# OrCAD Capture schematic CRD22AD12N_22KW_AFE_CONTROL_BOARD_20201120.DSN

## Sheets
1 P4 Output voltage sampling: size A3; title: 22kW Three Phase Bi-directional AFE ACDC Control Board; rev: 0v1; note: P/N: CRD22AD12N
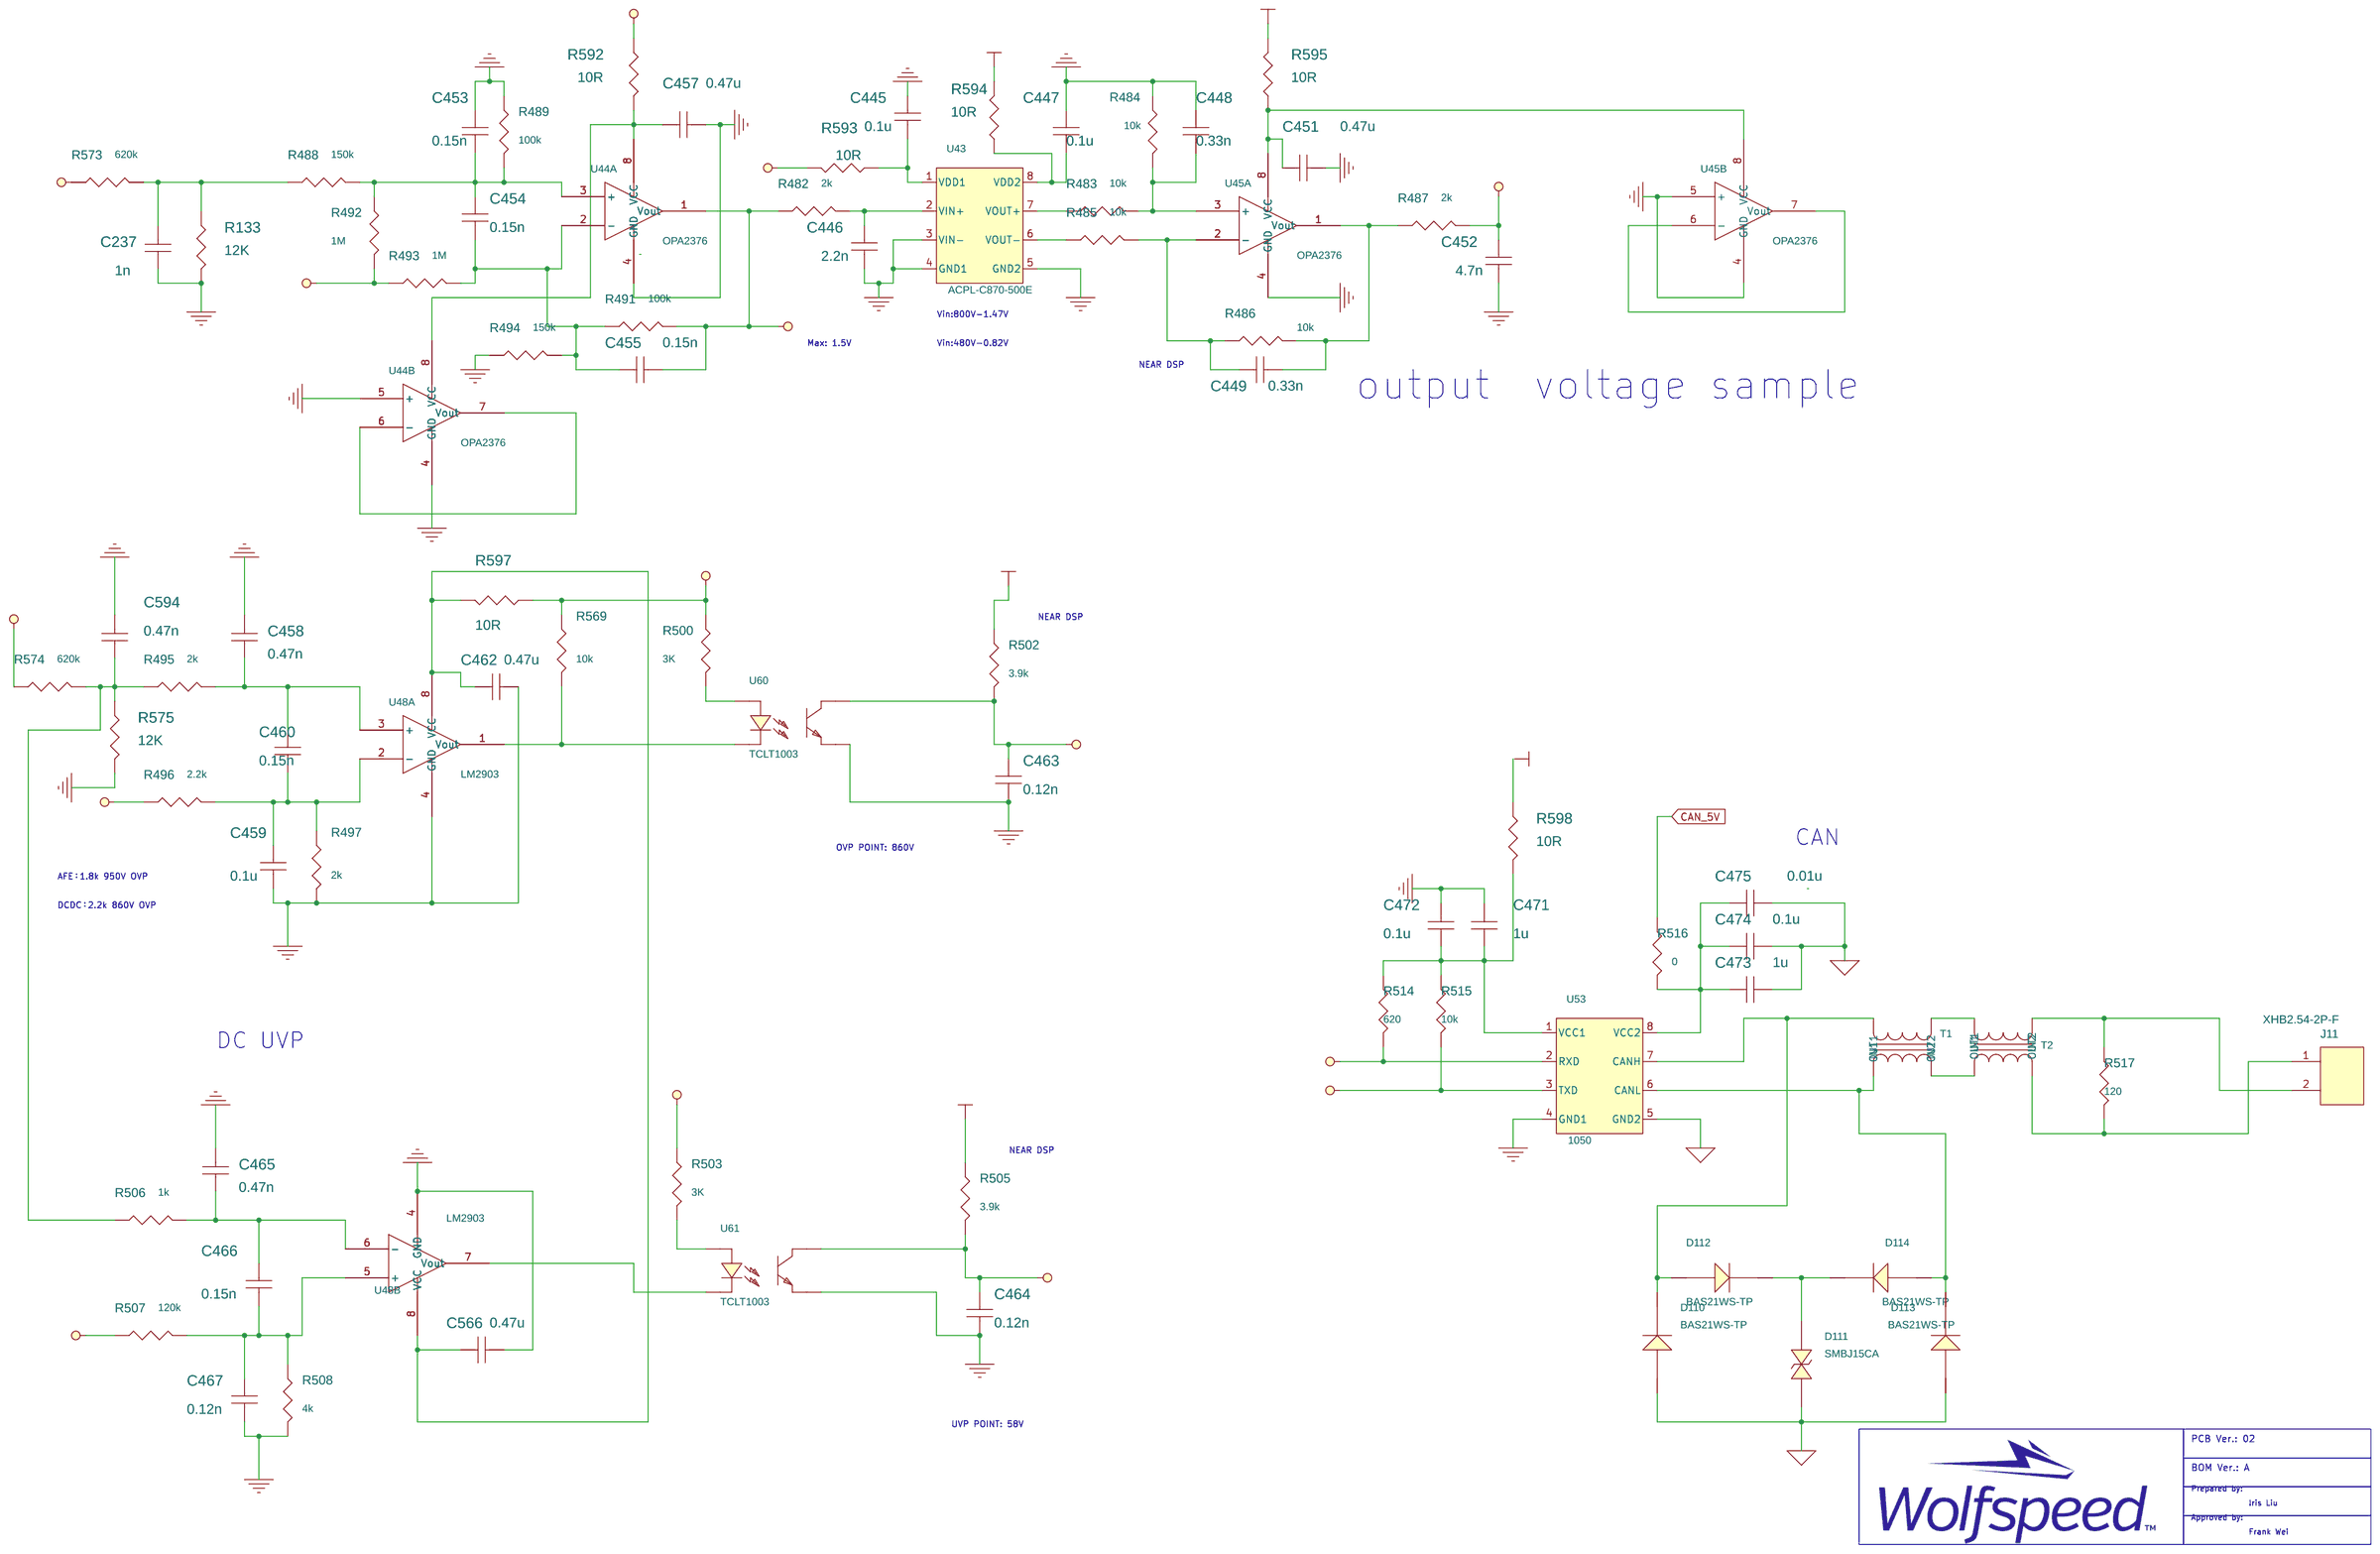
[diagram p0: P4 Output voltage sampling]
2 P3 Connector and Power supply: size A3
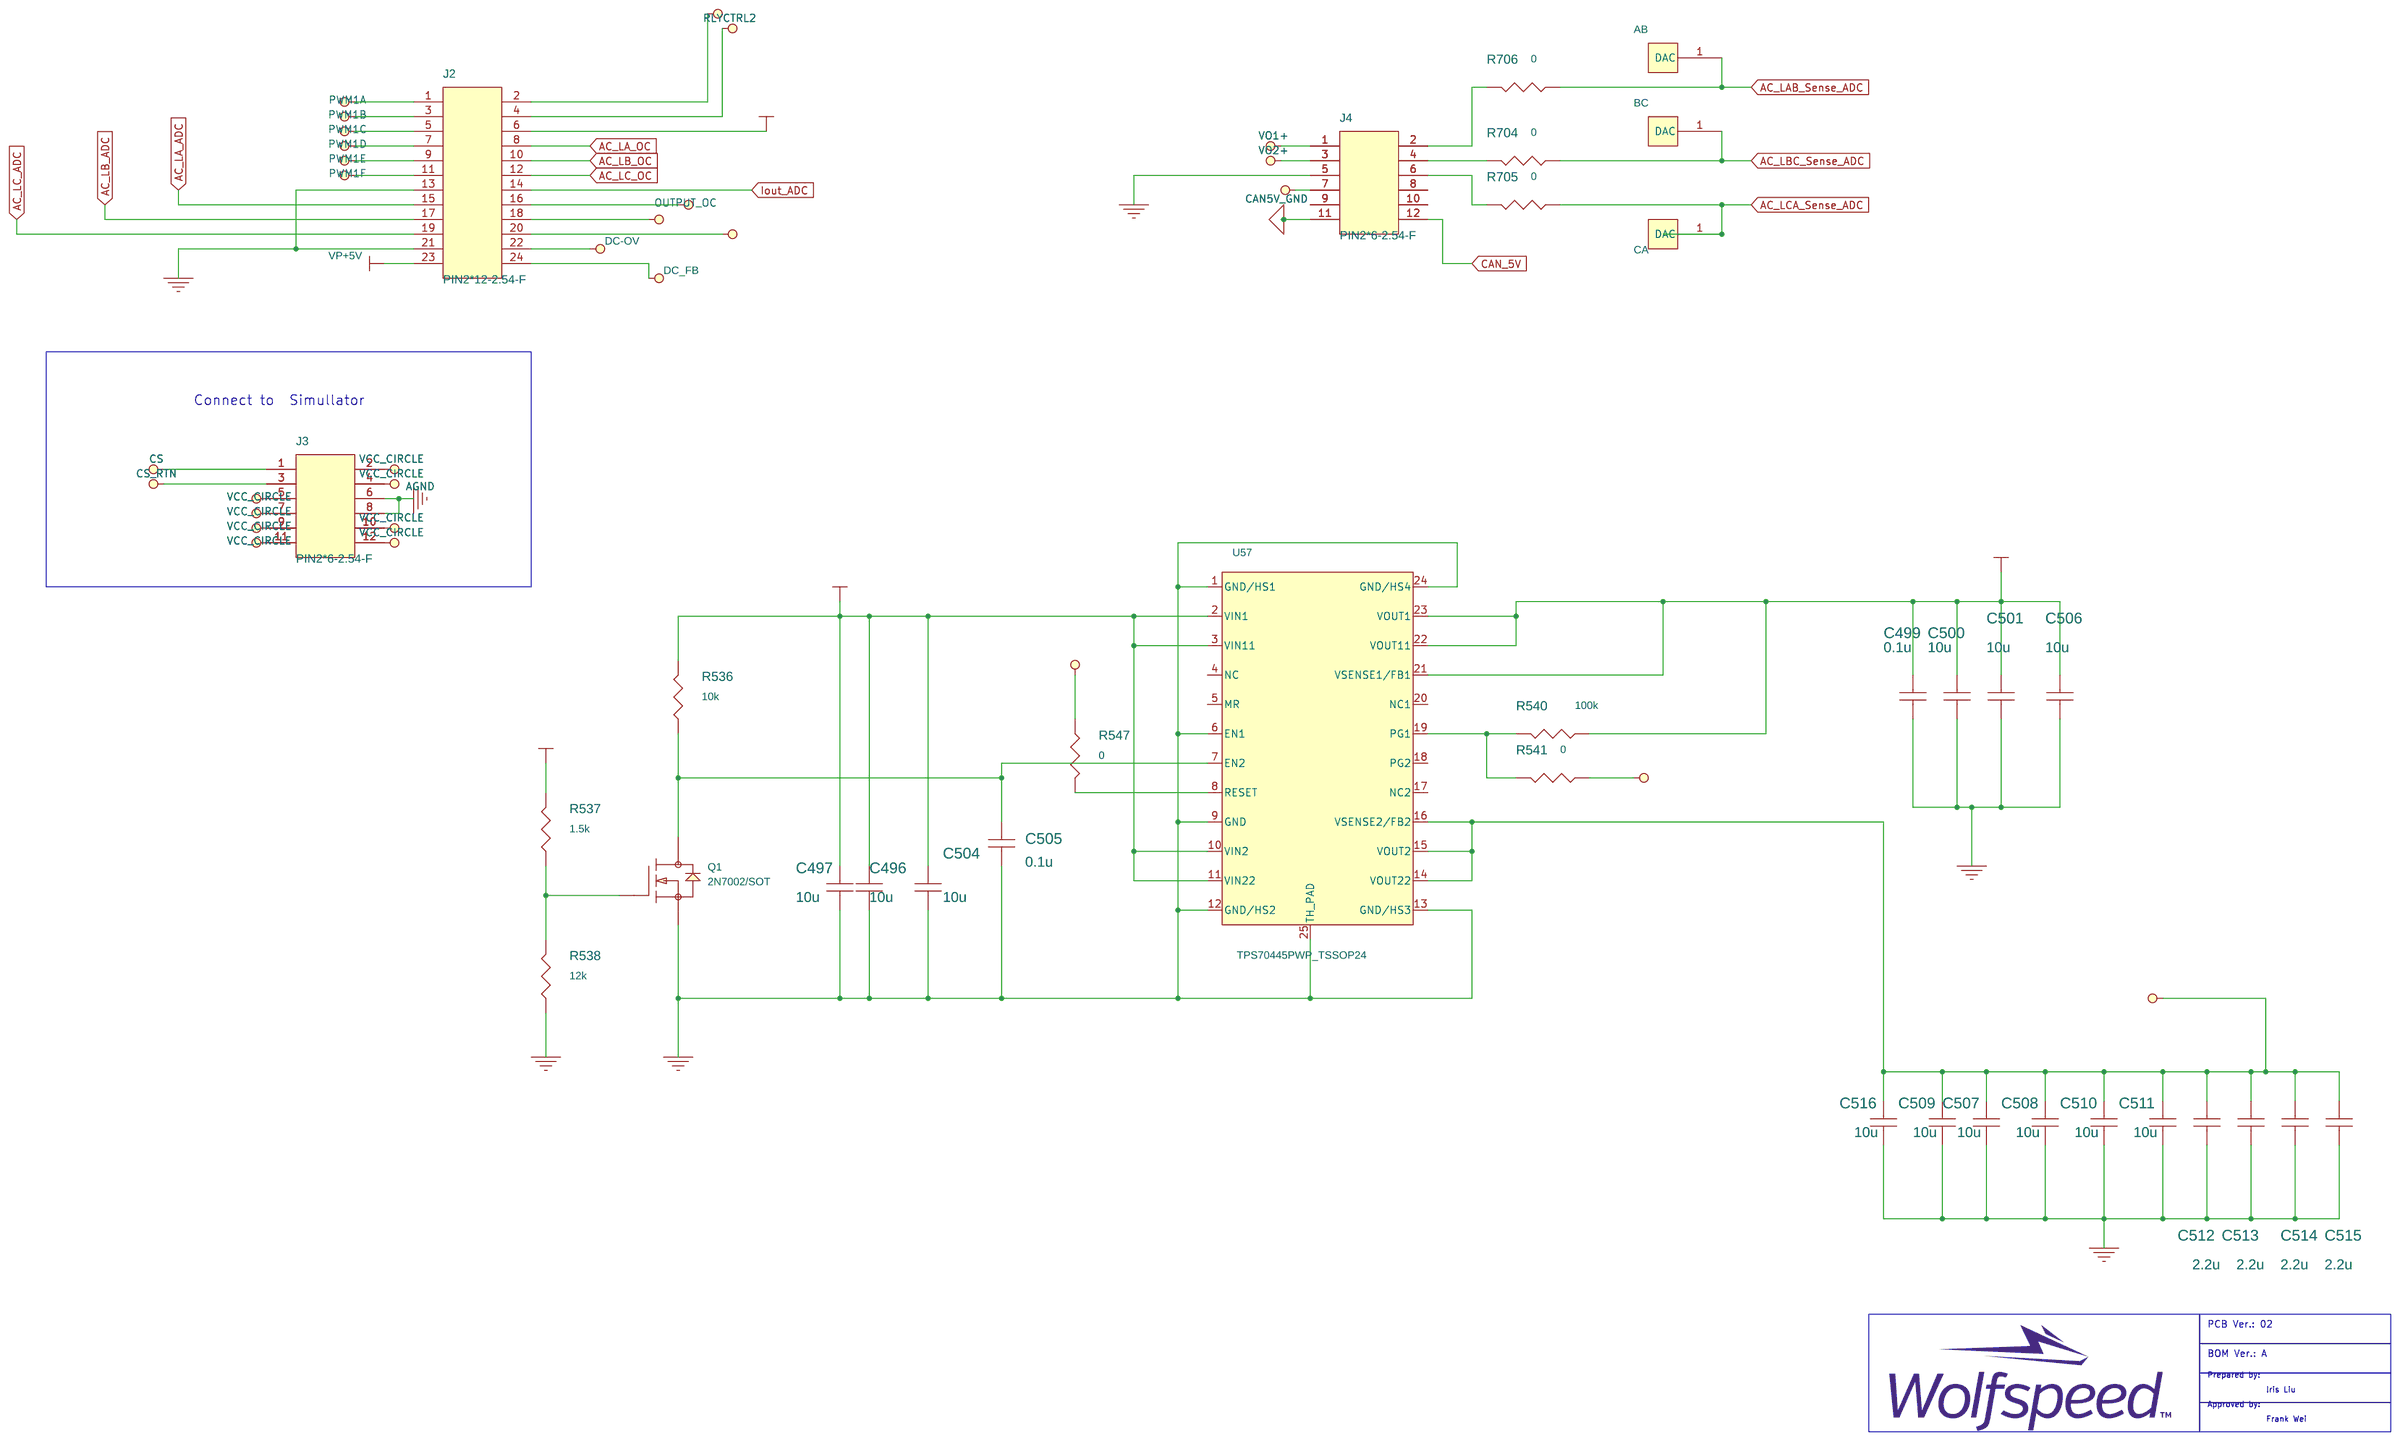
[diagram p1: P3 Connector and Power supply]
3 P2 Bus voltage sampling EPROM: size A3
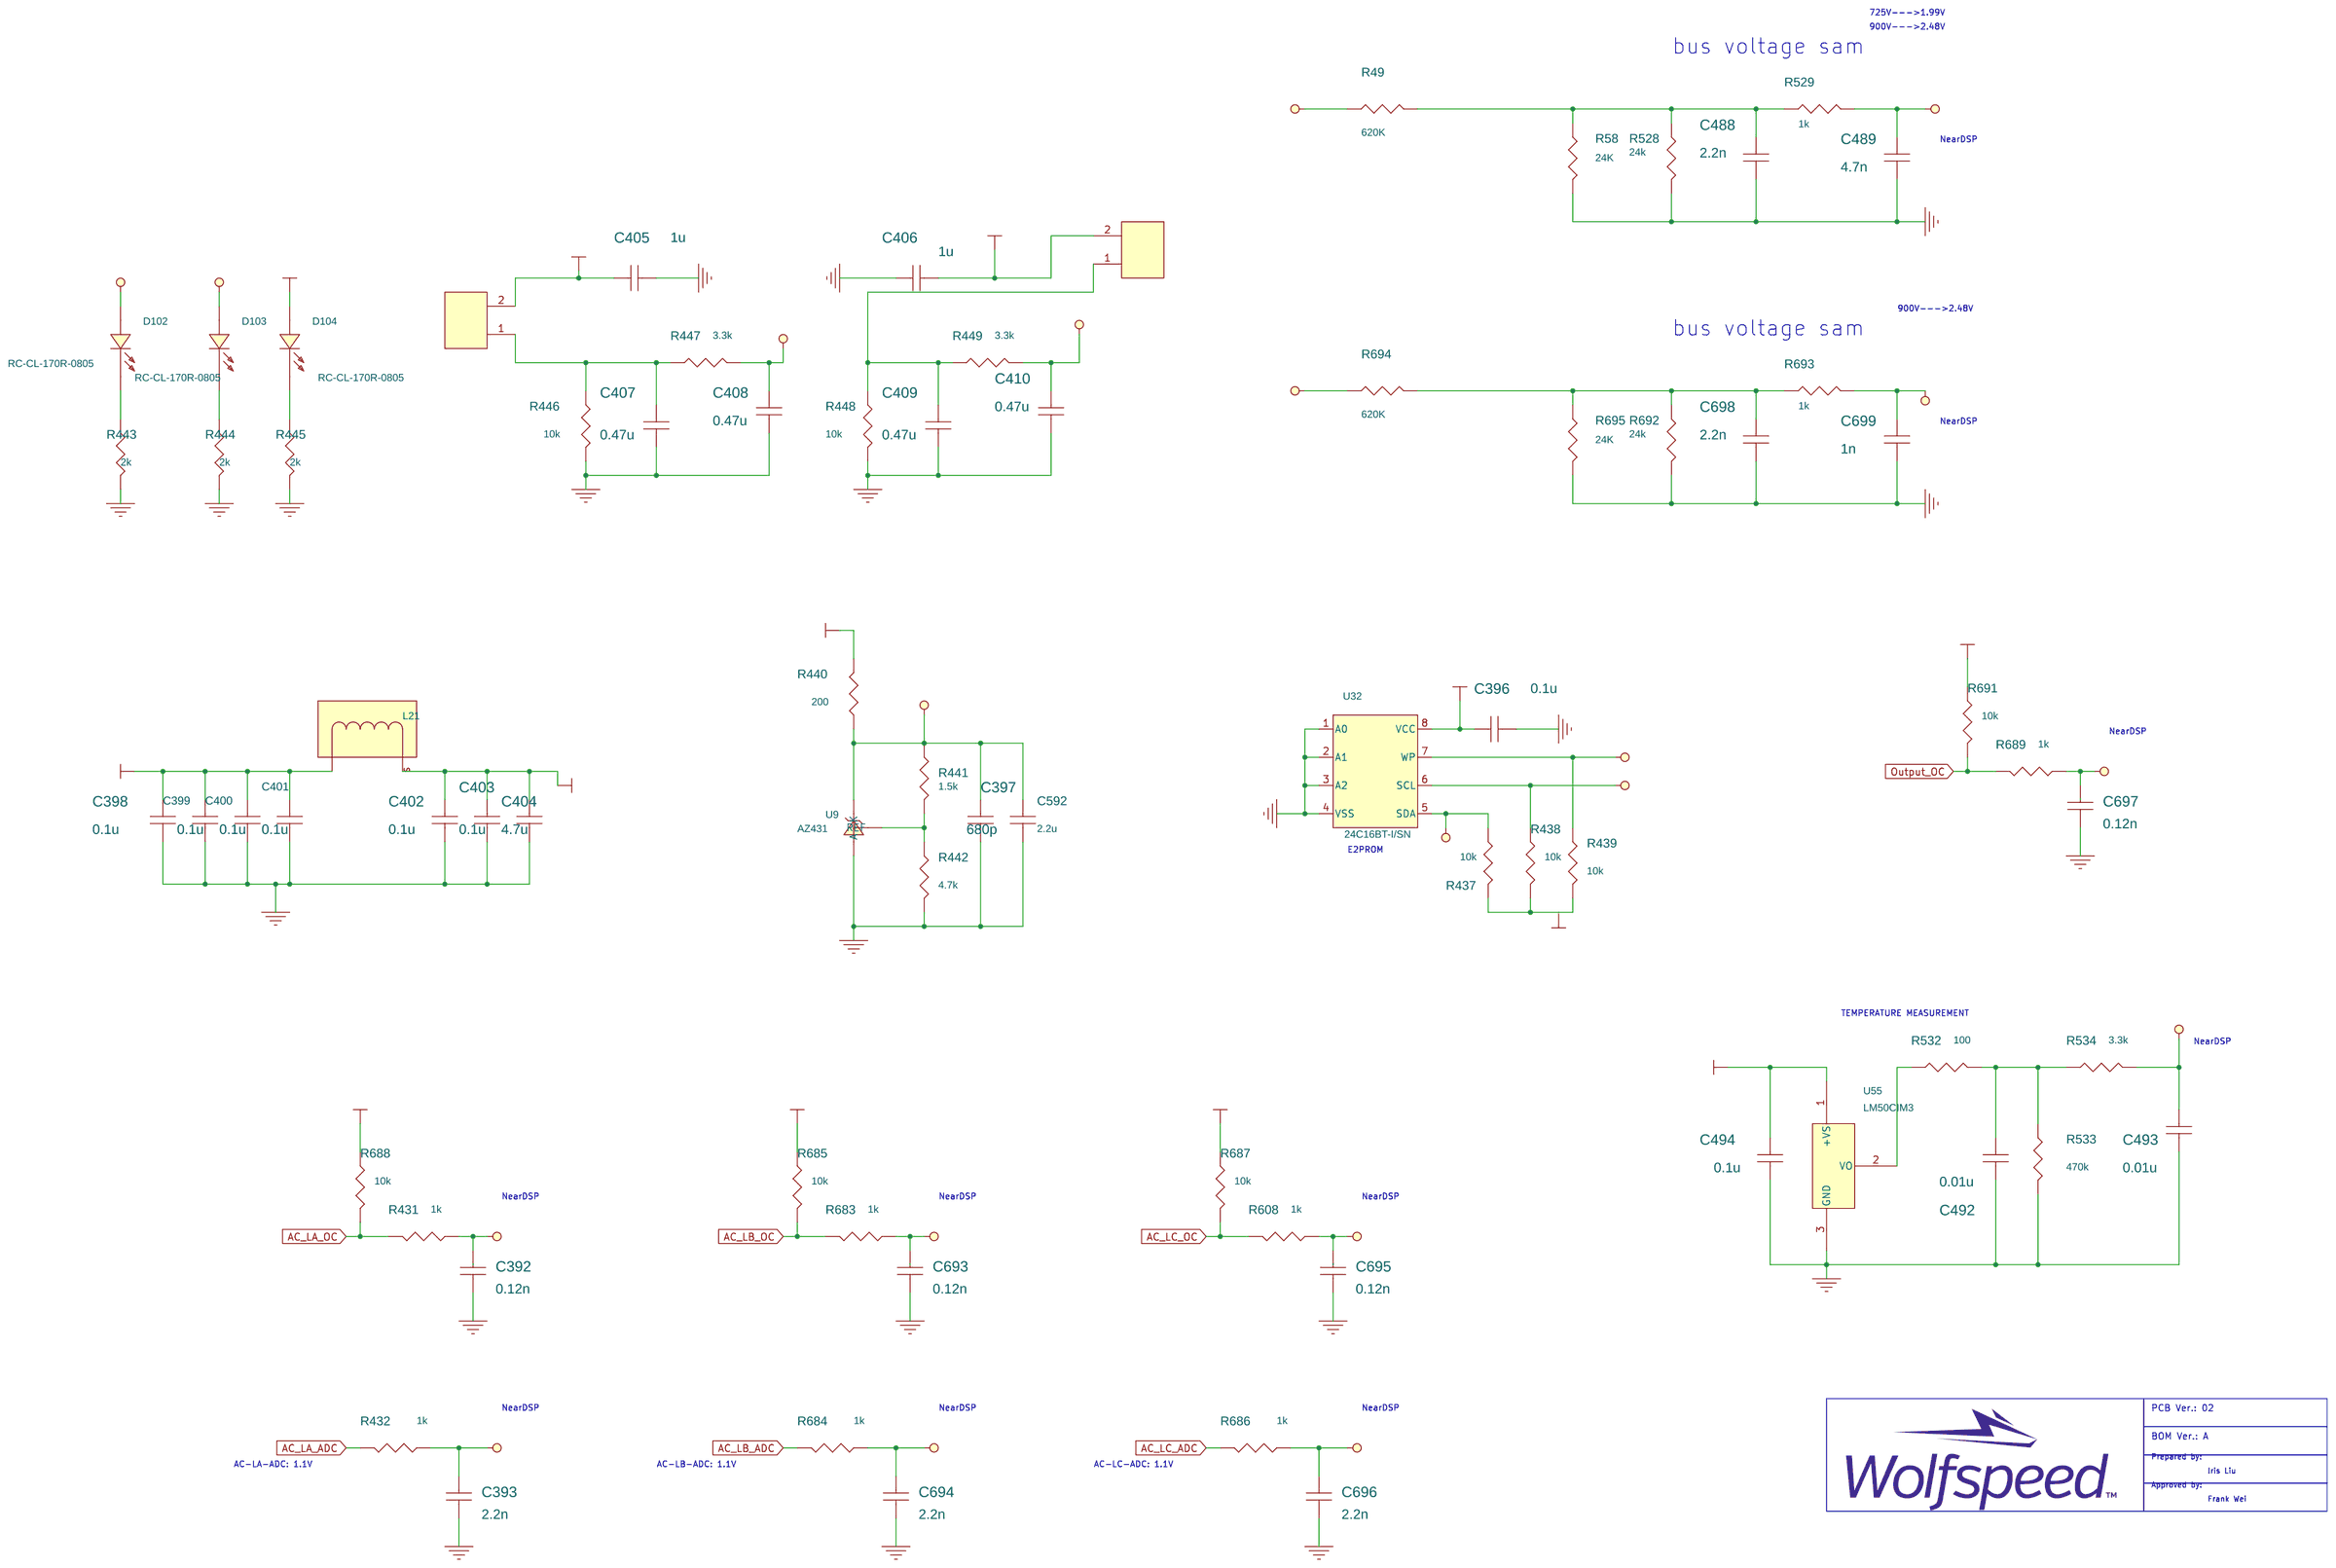
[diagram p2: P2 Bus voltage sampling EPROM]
4 P1 Controller: size C
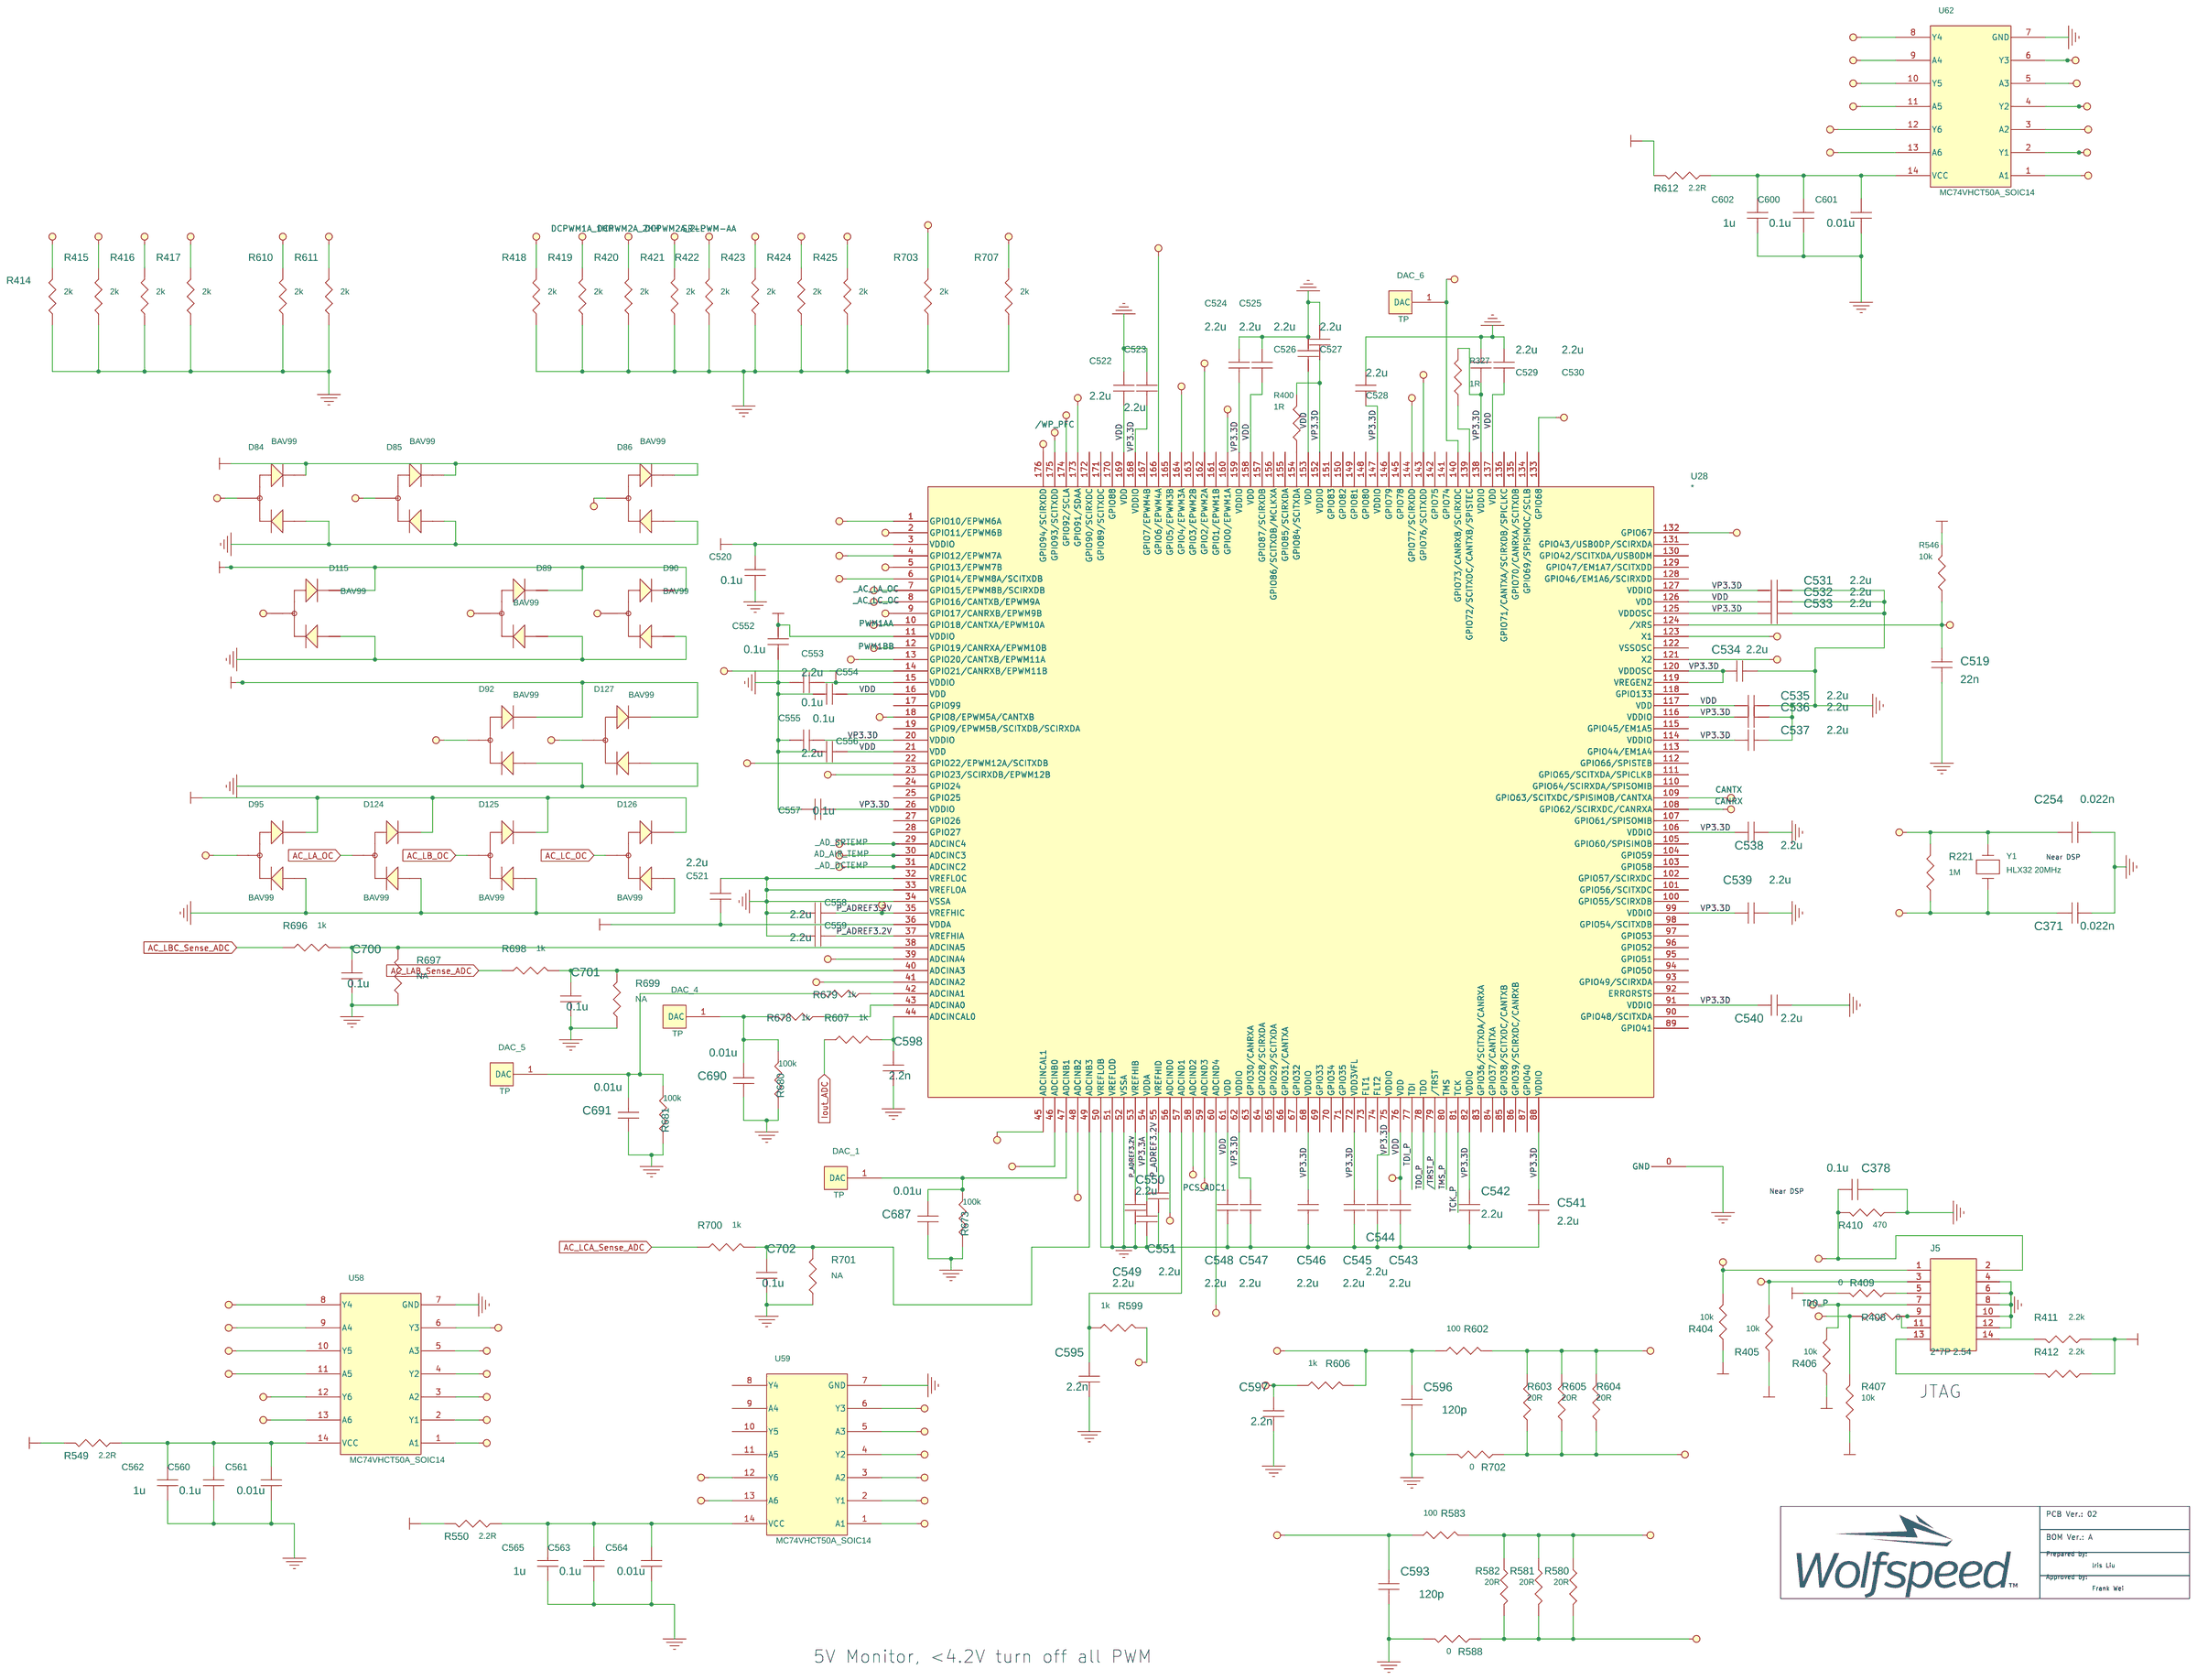
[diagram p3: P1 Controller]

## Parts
sheet P1 Controller
C254  0.022n  [C0603]
C371  0.022n  [C0603]
C378  0.1u  [C0603]
C519  22n  [C0603]
C520  0.1u  [C0603]
C521  2.2u  [C0603]
C522  2.2u  [C0603]
C523  2.2u  [C0603]
C524  2.2u  [C0603]
C525  2.2u  [C0603]
C526  2.2u  [C0603]
C527  2.2u  [C0603]
C528  2.2u  [C0603]
C529  2.2u  [C0603]
C530  2.2u  [C0603]
C531  2.2u  [C0603]
C532  2.2u  [C0603]
C533  2.2u  [C0603]
C534  2.2u  [C0603]
C535  2.2u  [C0603]
C536  2.2u  [C0603]
C537  2.2u  [C0603]
C538  2.2u  [C0603]
C539  2.2u  [C0603]
C540  2.2u  [C0603]
C541  2.2u  [C0603]
C542  2.2u  [C0603]
C543  2.2u  [C0603]
C544  2.2u  [C0603]
C545  2.2u  [C0603]
C546  2.2u  [C0603]
C547  2.2u  [C0603]
C548  2.2u  [C0603]
C549  2.2u  [C0603]
C550  2.2u  [C0603]
C551  2.2u  [C0603]
C552  0.1u  [C0603]
C553  0.1u  [C0603]
C554  2.2u  [C0603]
C555  0.1u  [C0603]
C556  2.2u  [C0603]
C557  0.1u  [C0603]
C558  2.2u  [C0603]
C559  2.2u  [C0603]
C560  0.1u  [C0603]
C561  0.01u  [C0603]
C562  1u  [C0603]
C563  0.1u  [C0603]
C564  0.01u  [C0603]
C565  1u  [C0603]
C593  120p  [C0603]
C595  2.2n  [C0603]
C596  120p  [C0603]
C597  2.2n  [C0603]
C598  2.2n  [C0603]
C600  0.1u  [C0603]
C601  0.01u  [C0603]
C602  1u  [C0603]
C687  0.01u  [C0603]
C690  0.01u  [C0603]
C691  0.01u  [C0603]
C700  0.1u  [C0603]
C701  0.1u  [C0603]
C702  0.1u  [C0603]
D84  BAV99  [SOT-23]
D85  BAV99  [SOT-23]
D86  BAV99  [SOT-23]
D89  BAV99  [SOT-23]
D90  BAV99  [SOT-23]
D92  BAV99  [SOT-23]
D95  BAV99  [SOT-23]
D115  BAV99  [SOT-23]
D124  BAV99  [SOT-23]
D125  BAV99  [SOT-23]
D126  BAV99  [SOT-23]
D127  BAV99  [SOT-23]
DAC_1  TP  [1mmTestpoint]
DAC_4  TP  [1mmTestpoint]
DAC_5  TP  [1mmTestpoint]
DAC_6  TP  [1mmTestpoint]
J5  2*7P 2.54  [con_2mm54_7x2]
R221  1M  [R0603]
R327  1R  [R0603]
R400  1R  [R0603]
R404  10k  [R0603]
R405  10k  [R0603]
R406  10k  [R0603]
R407  10k  [R0603]
R408  0  [R0603]
R409  0  [R0603]
R410  470  [R0603]
R411  2.2k  [R0603]
R412  2.2k  [R0603]
R414  2k  [R0603]
R415  2k  [R0603]
R416  2k  [R0603]
R417  2k  [R0603]
R418  2k  [R0603]
R419  2k  [R0603]
R420  2k  [R0603]
R421  2k  [R0603]
R422  2k  [R0603]
R423  2k  [R0603]
R424  2k  [R0603]
R425  2k  [R0603]
R546  10k  [R1206]
R549  2.2R  [R0603]
R550  2.2R  [R0603]
R580  20R  [R1206]
R581  20R  [R1206]
R582  20R  [R1206]
R583  100  [R0603]
R588  0  [R0603]
R599  1k  [R0603]
R602  100  [R0603]
R603  20R  [R1206]
R604  20R  [R1206]
R605  20R  [R1206]
R606  1k  [R0603]
R607  1k  [R0603]
R610  2k  [R0603]
R611  2k  [R0603]
R612  2.2R  [R0603]
R673  100k  [R0603]
R678  1k  [R0603]
R679  1k  [R0603]
R680  100k  [R0603]
R681  100k  [R0603]
R696  1k  [R0603]
R697  NA  [R0603]
R698  1k  [R0603]
R699  NA  [R0603]
R700  1k  [R0603]
R701  NA  [R0603]
R702  0  [R0603]
R703  2k  [R0603]
R707  2k  [R0603]
U28  TMS320F28377D  [LQFP176-050-2424]
U58  MC74VHCT50A_SOIC14  [SOIC14]
U59  MC74VHCT50A_SOIC14  [SOIC14]
U62  MC74VHCT50A_SOIC14  [SOIC14]
Y1  HLX32 20MHz  [TSX-3225]
sheet P2 Bus voltage sampling EPROM
C392  0.12n  [C0603]
C393  2.2n  [C0603]
C396  0.1u  [C0603]
C397  680p  [C0603]
C398  0.1u  [C0603]
C399  0.1u  [C0603]
C400  0.1u  [C0603]
C401  0.1u  [C0603]
C402  0.1u  [C0603]
C403  0.1u  [C0603]
C404  4.7u  [c1206]
C405  1u  [C0603]
C406  1u  [C0603]
C407  0.47u  [C0603]
C408  0.47u  [C0603]
C409  0.47u  [C0603]
C410  0.47u  [C0603]
C488  2.2n  [C0603]
C489  4.7n  [C0603]
C492  0.01u  [C0603]
C493  0.01u  [C0603]
C494  0.1u  [C0603]
C592  2.2u  [C0805]
C693  0.12n  [C0603]
C694  2.2n  [C0603]
C695  0.12n  [C0603]
C696  2.2n  [C0603]
C697  0.12n  [C0603]
C698  2.2n  [C0603]
C699  1n  [C0603]
D102  RC-CL-170R-0805  [led0805]
D103  RC-CL-170R-0805  [led0805]
D104  RC-CL-170R-0805  [led0805]
J17  1*2P  [connect_2mm54_2x1]
J18  1*2P  [connect_2mm54_2x1]
L21  33uH 0.2A  [R0805]
R49  620K  [R1206]
R58  24K  [R0603]
R431  1k  [R0603]
R432  1k  [R0603]
R437  10k  [R0603]
R438  10k  [R0603]
R439  10k  [R0603]
R440  200  [R0603]
R441  1.5k  [R0603]
R442  4.7k  [R0603]
R443  2k  [R0603]
R444  2k  [R0603]
R445  2k  [R0603]
R446  10k  [R0603]
R447  3.3k  [R0603]
R448  10k  [R0603]
R449  3.3k  [R0603]
R528  24k  [R0603]
R529  1k  [R0603]
R532  100  [R0603]
R533  470k  [R0603]
R534  3.3k  [R0603]
R608  1k  [R0603]
R683  1k  [R0603]
R684  1k  [R0603]
R685  10k  [R0603]
R686  1k  [R0603]
R687  10k  [R0603]
R688  10k  [R0603]
R689  1k  [R0603]
R691  10k  [R0603]
R692  24k  [R0603]
R693  1k  [R0603]
R694  620K  [R1206]
R695  24K  [R0603]
U9  AZ431  [SOT23_1-32]
U32  24C16BT-I/SN  [SOIC-8]
U55  LM50CIM3  [SOT-23]
sheet P3 Connector and Power supply
AB  TP  [1mmTestpoint]
BC  TP  [1mmTestpoint]
C496  10u  [C1206]
C497  10u  [C1206]
C499  0.1u  [C0603]
C500  10u  [c1206]
C501  10u  [c1206]
C504  10u  [C1206]
C505  0.1u  [C0603]
C506  10u  [c1206]
C507  10u  [C1206]
C508  10u  [C1206]
C509  10u  [C1206]
C510  10u  [C1206]
C511  10u  [C1206]
C512  2.2u  [C0805]
C513  2.2u  [C0805]
C514  2.2u  [C0805]
C515  2.2u  [C0805]
C516  10u  [C1206]
CA  TP  [1mmTestpoint]
J2  PIN2*12-2.54-F  [con_2mm54_12x2]
J3  PIN2*6-2.54-F  [con_2mm54_6x2]
J4  PIN2*6-2.54-F  [con_2mm54_6x2]
Q1  2N7002/SOT  [SOT-23]
R536  10k  [R0603]
R537  1.5k  [R0603]
R538  12k  [R0603]
R540  100k  [R0603]
R541  0  [R0603]
R547  0  [R0603]
R704  0  [R0603]
R705  0  [R0603]
R706  0  [R0603]
U57  TPS70445PWP_TSSOP24  [TSSOP24]
sheet P4 Output voltage sampling
C237  1n  [C0603]
C445  0.1u  [C0603]
C446  2.2n  [C0603]
C447  0.1u  [C0603]
C448  0.33n  [C0603]
C449  0.33n  [C0603]
C451  0.47u  [C0603]
C452  4.7n  [C0603]
C453  0.15n  [C0603]
C454  0.15n  [C0603]
C455  0.15n  [C0603]
C457  0.47u  [C0603]
C458  0.47n  [C0603]
C459  0.1u  [C0603]
C460  0.15n  [C0603]
C462  0.47u  [C0603]
C463  0.12n  [C0603]
C464  0.12n  [C0603]
C465  0.47n  [C0603]
C466  0.15n  [C0603]
C467  0.12n  [C0603]
C471  1u  [C0603]
C472  0.1u  [C0603]
C473  1u  [C0603]
C474  0.1u  [C0603]
C475  0.01u  [C0603]
C566  0.47u  [C0603]
C594  0.47n  [C0603]
D110  BAS21WS-TP  [SOD-323]
D111  SMBJ15CA  [SMB]
D112  BAS21WS-TP  [SOD-323]
D113  BAS21WS-TP  [SOD-323]
D114  BAS21WS-TP  [SOD-323]
J11  XHB2.54-2P-F  [con_2mm54_2x1]
R133  12K  [R0603]
R482  2k  [R0603]
R483  10k  [R0603]
R484  10k  [R0603]
R485  10k  [R0603]
R486  10k  [R0603]
R487  2k  [R0603]
R488  150k  [R0603]
R489  100k  [R0603]
R491  100k  [R0603]
R492  1M  [R0603]
R493  1M  [R0603]
R494  150k  [R0603]
R495  2k  [R0603]
R496  2.2k  [R0603]
R497  2k  [R0603]
R500  3K  [R0603]
R502  3.9k  [R0603]
R503  3K  [R0603]
R505  3.9k  [R0603]
R506  1k  [R0603]
R507  120k  [R0603]
R508  4k  [R0603]
R514  620  [R0603]
R515  10k  [R0603]
R516  0  [R0603]
R517  120  [R0603]
R569  10k  [R0603]
R573  620k  [R1206]
R574  620k  [R1206]
R575  12K  [R0603]
R592  10R  [R0603]
R593  10R  [R0603]
R594  10R  [R0603]
R595  10R  [R0603]
R597  10R  [R0603]
R598  10R  [R0603]
T1  TRNSFMR TV105  [4532]
T2  TRNSFMR TV105  [4532]
U43  ACPL-C870-500E  [SSO-8]
U44  OPA2376  [SOIC-8]  (sections A,B)
U45  OPA2376  [SOIC-8]  (sections A,B)
U48  LM2903  [SOIC-8]  (sections A,B)
U53  1050  [SO-G8]
U60  TCLT1003  [tclt1003]
U61  TCLT1003  [tclt1003]

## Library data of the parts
C237 C254 C371 C378 C392 C393 C396-C410 C445-C449 C451-C455 C457-C460 C462-C467 C471-C475 C488 C489 C492-C494 C496 C497 C499-C501 C504-C516 C519-C566 C592-C598 C600-C602 C687 C690 C691 C693-C702 = CAP_NP
D84-D86 D89 D90 D92 D95 D115 D124-D127 = BAS70-04_SOT
AB BC CA DAC_1 DAC_4-DAC_6 = TP
J5 = 2*7P: Part Label: 2*7P 2.54 直针; Part number: 621000812; Part_Name: 连接器; Unit: PCS
R49 R58 R221 R404-R412 R414-R425 R431 R432 R437-R449 R482-R489 R491-R497 R500 R502 R503 R505-R508 R514-R517 R528 R529 R532-R534 R536-R538 R540 R541 R547 R549 R550 R569 R573 R574 R580-R583 R588 R599 R602-R608 R610-R612 R673 R678-R681 R683-R689 R691-R707 = RESISTOR
R133 R327 R400 R546 R575 R592-R595 R597 R598 = R
U28 = TMS320F28377D: Comment_1: *; Manufacturers Part: TI; Part number: 606800054; Type: IC
U58 U59 U62 = MC74VHCT50A_SOIC14
Y1 = CRYSTAL2-4_SM_0
D102-D104 = CCL-CRS10_SM
J17 J18 = 1*2P
L21 = 126LNS_4
U9 = LEU094_ZTL431AFTA_SOT23_0: LLF Part Number: LEU072
U32 = 24C16BT-I_SN
U55 = MC78L05F-TP_0
J2 = 2*12P: Part Label: PIN2*12-2.54-F 直针; Part number: 621000132; Part_Name: 双排直针; Unit: PCS
J3 J4 = 2*6P: Part Label: PIN2*6-2.54-F 直针; Part number: 621000134; Part_Name: 双排直针; Unit: PCS
Q1 = 2N7002_SOT
U57 = TPS70445PWP_TSSOP24
D110 = BAS21_SOT_1
D111 = DIODE_BI-DIR_TRIG
D112 = BAS21_SOT_2
D113 = BAS21_SOT_4
D114 = BAS21_SOT_3
J11 = 1*2P: Manufacturers Part: 浙江硕正电气; Part Label: connect_2mm54_2x1; Part number: 621000044; Part_Name: 插座; Unit: PCS
T1 T2 = TRNSFMR_TV105_0
U43 = 24C16BT-I_SN_0
U44 U45 U48 = LM2904
U53 = 24C16BT-I_SN_2
U60 U61 = LEU169_TCLT1003_SOP-4L

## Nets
AGND: C254.1 C371.1 C378.2 C392.2 C393.2 C396.2 C397.2 C398.2 C399.2 C400.2 C401.2 C402.2 C403.2 C404.2 C405.2 C406.1 C407.2 C408.2 C409.2 C410.2 C447.1 C448.1 C451.2 C452.2 C463.2 C464.2 C471.2 C472.2 C488.2 C489.2 C492.2 C493.2 C494.2 C496.2 C497.2 C499.2 C500.2 C501.2 C504.2 C505.2 C506.2 C507.2 C508.2 C509.2 C510.2 C511.2 C512.2 C513.2 C514.2 C515.2 C516.2 C519.2 C520.2 C521.2 C522.1 C523.1 C524.1 C525.1 C526.1 C527.1 C528.1 C529.1 C530.1 C531.2 C532.2 C533.2 C534.2 C535.2 C536.2 C537.2 C538.2 C539.2 C540.2 C541.1 C542.1 C543.1 C544.1 C545.1 C546.1 C547.1 C548.1 C549.1 C550.1 C551.1 C552.2 C553.1 C554.1 C555.1 C556.1 C557.1 C558.1 C559.1 C560.2 C561.2 C562.2 C563.2 C564.2 C565.2 C592.2 C593.2 C595.2 C596.2 C597.2 C598.2 C600.2 C601.2 C602.2 C687.1 C690.1 C691.1 C693.2 C694.2 C695.2 C696.2 C697.2 C698.2 C699.2 C700.2 C701.2 C702.2 D84.1 D85.1 D86.1 D89.1 D90.1 D92.1 D95.1 D115.1 D124.1 D125.1 D126.1 D127.1 J2.13 J2.21 J3.6 J3.8 J5.4 J5.6 J5.8 J5.10 J5.12 Q1.2(SOURCE) R58.1 R410.1 R414.1 R415.1 R416.1 R417.1 R418.1 R419.1 R420.1 R421.1 R422.1 R423.1 R424.1 R425.1 R442.2 R443.2 R444.2 R445.2 R446.2 R448.2 R484.1 R528.2 R533.2 R538.1 R588.2 R610.1 R611.1 R673.1 R680.1 R681.1 R692.2 R695.1 R697.1 R699.1 R701.1 R702.2 R703.1 R707.1 U9.3(A) U28.0(GND) U28.32(VREFLOC) U28.33(VREFLOA) U28.34(VSSA) U28.50(VREFLOB) U28.51(VREFLOD) U28.52(VSSA) U32.1(A0) U32.2(A1) U32.3(A2) U32.4(VSS) U43.5(GND2) U45.4(GND) U45.5(+) U53.4(GND1) U55.3(GND) U57.1(GND/HS1) U57.6(EN1) U57.9(GND) U57.12(GND/HS2) U57.13(GND/HS3) U57.24(GND/HS4) U57.25(TH_PAD) U58.7(GND) U59.7(GND) U60.3 U61.3 U62.7(GND)
SGND: C237.1 C445.1 C446.2 C453.1 C457.2 C458.2 C459.2 C462.2 C465.2 C467.2 C566.2 C594.2 J4.5 R133.2 R489.1 R494.1 R497.2 R508.2 R575.2 U43.3(VIN-) U43.4(GND1) U44.4(GND) U44.5(+) U48.4(GND)
VDD: C507.1 C508.1 C509.1 C510.1 C511.1 C512.1 C513.1 C514.1 C515.1 C516.1 C522.2 C525.2 C526.2 C530.2 C532.1 C535.1 C543.2 C548.2 C554.2 C556.2 U28.16(VDD) U28.21(VDD) U28.61(VDD) U28.76(VDD) U28.117(VDD) U28.126(VDD) U28.137(VDD) U28.153(VDD) U28.158(VDD) U28.169(VDD) U57.14(VOUT22) U57.15(VOUT2) U57.16(VSENSE2/FB2)
/TRST_P: C378.1 J5.2 R410.2 U28.79(/TRST)
/WP_PFC: R439.1 U28.175(GPIO93/SCITXDD) U32.7(WP)
_AC_LA_ADC: C393.1 R432.1 U28.41(ADCINA2)
_AC_LA_OC: C392.1 R431.1 U28.7(GPIO15/EPWM8B/SCIRXDB)
_AC_LB_ADC: C694.1 R684.1 U28.39(ADCINA4)
_AC_LB_OC: C693.1 R683.1 U28.9(GPIO17/CANRXB/EPWM9B)
_AC_LC_ADC: C696.1 R686.1 U28.48(ADCINB2)
_AC_LC_OC: C695.1 C697.1 R608.1 R689.1 U28.8(GPIO16/CANTXB/EPWM9A)
_AD_DCinput: C489.1 D115.3 R529.2 U28.46(ADCINB0)
_AD_DCinput_OV: C699.1 D86.3 R693.2 U28.60(ADCIND4)
_AD_DCTEMP: C408.1 D92.3 R447.2 U28.31(ADCINC2)
_AD_SRTEMP: C410.1 D84.3 R449.2 U28.29(ADCINC4)
AC_LA_ADC: J2.15 R432.2
AC_LA_OC: D124.3 J2.8 R431.2 R688.2
AC_LAB_Sense_ADC: AB.1(DAC) R698.1 R706.1
AC_LB_ADC: J2.17 R684.2
AC_LB_OC: D125.3 J2.10 R683.2 R685.2
AC_LBC_Sense_ADC: BC.1(DAC) R696.1 R704.1
AC_LC_ADC: J2.19 R686.2
AC_LC_OC: D126.3 J2.12 R608.2 R687.2
AC_LCA_Sense_ADC: CA.1(DAC) R700.1 R705.1
AD_AIR_TEMP: C493.1 D85.3 R534.2 U28.30(ADCINC3)
AD_DCVOLT1: C452.1 D89.3 R487.2 U28.45(ADCINCAL1)
CAN5V_GND: C473.2 C474.2 C475.2 D110.1(ANODE) D111.1 D113.1(ANODE) J4.11 U53.5(GND2)
CAN_5V: J4.12 R516.1
CANRX: R514.2 U28.108(GPIO62/SCIRXDC/CANRXA) U53.2(RXD)
CANTX: R515.2 U28.109(GPIO63/SCITXDC/SPISIMOB/CANTXA) U53.3(TXD)
CS: J3.1 R580.2 R581.2 R582.2 R583.1
CS_ADC: C593.1 D127.3 R583.2 R599.1 U28.56(ADCIND0)
CS_Pri: J2.18 R602.1 R603.2 R604.2 R605.2
CS_RTN: J3.3 R580.1 R581.1 R582.1 R588.1
CS_RTN_pri: J2.20 R603.1 R604.1 R605.1 R702.1
DC-OV: J2.22 R694.2
DC_FB: J2.24 R49.2
DCOVP: C463.1 R502.2 U28.176(GPIO94/SCIRXDD) U60.4
DCPWM1A_1H: J3.4 U58.6(Y3)
DCPWM1A_1HH: R419.2 U28.160(GPIO0/EPWM1A) U58.5(A3)
DCPWM1A_1L: J3.2 U58.4(Y2)
DCPWM1A_1LL: R418.2 U28.162(GPIO2/EPWM2A) U58.3(A2)
DCPWM2A_2H: J3.7 U58.12(Y6)
DCPWM2A_2HH: R420.2 U28.164(GPIO4/EPWM3A) U58.13(A6)
DCPWM2A_2L: J3.5 U58.2(Y1)
DCPWM2A_2LL: R421.2 U28.166(GPIO6/EPWM4A) U58.1(A1)
DCSHORT: C464.1 R505.2 U28.5(GPIO13/EPWM7B) U61.4
DCVOLT1: C455.2 R482.1 R491.2 U44.1(Vout)
Iout_ADC: J2.14 R607.1
Output_OC: D95.3 J2.16 U28.2(GPIO11/EPWM6B)
Output_OC (page P2 Bus voltage sampling EPROM): R689.2 R691.2
P_ADREF3.2V: C397.1 C549.2 C551.2 C558.2 C559.2 C592.1 R440.1 R441.1 U9.2(K) U28.35(VREFHIC) U28.37(VREFHIA) U28.53(VREFHIB) U28.55(VREFHID)
P_SCL: R438.1 U28.174(GPIO92/SCLA) U32.6(SCL)
P_SDA: R437.1 U28.173(GPIO91/SDAA) U32.5(SDA)
P_WD_GREEN: D102.2(ANODE) U28.143(GPIO76/SCITXDD)
P_WD_RED: D103.2(ANODE) U28.144(GPIO77/SCIRXDD)
PCS_ADC: C596.1 D90.3 R602.2 R606.1 U28.58(ADCIND2)
PCS_ADC1: C597.1 R606.2 U28.59(ADCIND3)
PWM1A: J2.1 U62.8(Y4)
PWM1AA: R414.2 U28.10(GPIO18/CANTXA/EPWM10A) U62.9(A4)
PWM1B: J2.3 U62.10(Y5)
PWM1BB: R415.2 U28.12(GPIO19/CANRXA/EPWM10B) U62.11(A5)
PWM1C: J2.5 U62.12(Y6)
PWM1CC: R416.2 R610.2 U28.13(GPIO20/CANTXB/EPWM11A) U62.13(A6)
PWM1D: J2.7 U62.6(Y3)
PWM1DD: R417.2 R611.2 U28.14(GPIO21/CANRXB/EPWM11B) U62.5(A3)
PWM1E: J2.9 U62.4(Y2)
PWM1EE: U28.22(GPIO22/EPWM12A/SCITXDB) U62.3(A2)
PWM1F: J2.11 U62.2(Y1)
PWM1FF: U28.23(GPIO23/SCIRXDB/EPWM12B) U62.1(A1)
RLYCTRL1: J2.2 U58.10(Y5)
RLYCTRL2: J2.4 U58.8(Y4)
RLYCTRL11: R703.2 U28.133(GPIO68) U58.11(A5)
RLYCTRL22: R707.2 U28.132(GPIO67) U58.9(A4)
SR-PWM-A: J3.9 U59.12(Y6)
SR-PWM-AA: R422.2 U28.18(GPIO8/EPWM5A/CANTXB) U59.13(A6)
SR-PWM-B: J3.10 U59.2(Y1)
SR-PWM-BB: R423.2 U28.1(GPIO10/EPWM6A) U59.1(A1)
SR-PWM-C: J3.11 U59.4(Y2)
SR-PWM-CC: R424.2 U28.4(GPIO12/EPWM7A) U59.3(A2)
SR-PWM-D: J3.12 U59.6(Y3)
SR-PWM-DD: R425.2 U28.6(GPIO14/EPWM8A/SCITXDB) U59.5(A3)
TCK_P: R407.2 R408.2 U28.81(TCK)
TDI_P: J5.3 R405.2 U28.77(TDI)
TDO_P: J5.7 R406.2 U28.78(TDO)
test: DAC_6.1(DAC) U28.140(GPIO73/CANRXB/SCIRXDC)
TMS_P: J5.1 R404.2 U28.80(TMS)
VO1+: J4.1 R574.1
VO2+: J4.3 R573.1
VP3.3A: C402.1 C403.1 C404.1 C521.1 C550.2 D84.2 D85.2 D86.2 D89.2 D90.2 D92.2 D115.2 D127.2 L21.1 U28.36(VDDA) U28.54(VDDA)
VP3.3D: C396.1 C398.1 C399.1 C400.1 C401.1 C405.1 C406.2 C499.1 C500.1 C501.1 C506.1 C520.1 C523.2 C524.2 C527.2 C528.2 C529.2 C531.1 C533.1 C534.1 C536.1 C537.1 C538.1 C539.1 C540.1 C541.2 C542.2 C544.2 C545.2 C546.2 C547.2 C552.1 C553.2 C555.2 C557.2 D95.2 D104.2(ANODE) D124.2 D125.2 D126.2 J2.6 J17.2 J18.2 L21.2 R327.2 R400.2 R404.1 R405.1 R406.1 R407.1 R409.2 R411.1 R412.1 R437.2 R438.2 R439.2 R502.1 R505.1 R537.2 R540.1 R546.2 R598.1 R685.1 R687.1 R688.1 R691.1 U28.3(VDDIO) U28.11(VDDIO) U28.15(VDDIO) U28.20(VDDIO) U28.26(VDDIO) U28.62(VDDIO) U28.68(VDDIO) U28.72(VDD3VFL) U28.75(VDDIO) U28.82(VDDIO) U28.88(VDDIO) U28.91(VDDIO) U28.99(VDDIO) U28.106(VDDIO) U28.114(VDDIO) U28.116(VDDIO) U28.119(VREGENZ) U28.120(VDDOSC) U28.125(VDDOSC) U28.127(VDDIO) U28.138(VDDIO) U28.147(VDDIO) U28.152(VDDIO) U28.159(VDDIO) U28.168(VDDIO) U32.8(VCC) U57.21(VSENSE1/FB1) U57.22(VOUT11) U57.23(VOUT1)
VP+5V: C494.1 C496.1 C497.1 C504.1 J2.23 R440.2 R536.2 R549.2 R550.2 R594.2 R595.2 R612.2 U55.1(+VS) U57.2(VIN1) U57.3(VIN11) U57.10(VIN2) U57.11(VIN22)
VS+5V: J4.7 R492.2 R493.1 R496.1 R500.1 R503.1 R507.1 R569.1 R592.2 R593.2 R597.1
X1: C371.2 R221.1 U28.123(X1) Y1.1(2)
X2: C254.2 R221.2 U28.121(X2) Y1.2(4)
XRS: C519.1 R541.1 R546.1 R547.1 U28.124(/XRS)
N16777869: J5.9 J5.11 R408.1
N16778586: C702.1 R700.2 R701.2 U28.49(ADCINB3)
N16779815: R327.1 U28.139(GPIO72/SCITXDC/CANTXB/SPISTEC)
N16809513: J5.5 R409.1
N16810933: J5.13 R412.2
N16810951: J5.14 R411.2
N16830570: R441.2 R442.1 U9.1(REF)
N16833081: D102.1(CATHODE) R443.1
N16833084: D103.1(CATHODE) R444.1
N16833087: D104.1(CATHODE) R445.1
N16835391: C407.1 J17.1 R446.1 R447.1
N16836592: C409.1 J18.1 R448.1 R449.1
N16848574: C446.1 R482.2 U43.2(VIN+)
N16848598: C445.2 R593.1 U43.1(VDD1)
N16848614: C447.2 R594.1 U43.8(VDD2)
N16848642: R483.1 U43.7(VOUT+)
N16848644: C448.2 R483.2 R484.2 U45.3(+)
N16848814: R485.1 U43.6(VOUT-)
N16848816: C449.1 R485.2 R486.1 U45.2(-)
N16848832: C449.2 R486.2 R487.1 U45.1(Vout)
N16848970: U44.6(-) U44.7(Vout)
N16848978: C453.2 C454.1 R488.2 R489.2 R492.1 U44.3(+)
N16848994: C454.2 C455.1 R491.1 R493.2 R494.2 U44.2(-)
N16849016: C457.1 R592.1 U44.8(VCC)
N16851028: U45.6(-) U45.7(Vout)
N16851046: C451.1 R595.1 U45.8(VCC)
N16853569: C458.1 C460.1 R495.2 U48.3(+)
N16853931: C459.1 C460.2 R496.2 R497.1 U48.2(-)
N16853972: R569.2 U48.1(Vout) U60.2
N16854025: C462.1 C566.1 R597.2 U48.8(VCC)
N16854569: R500.2 U60.1
N16855013: C466.2 C467.1 R507.2 R508.1 U48.5(+)
N16855828: C465.1 C466.1 R506.2 U48.6(-)
N16855912: U48.7(Vout) U61.2
N16855916: R503.2 U61.1
N16860426: C471.1 C472.1 R514.1 R515.1 R598.2 U53.1(VCC1)
N16860580: C473.1 C474.1 C475.1 R516.2 U53.8(VCC2)
N16860640: D110.2(CATHODE) D112.1(ANODE) T1.2(OUT1) U53.7(CANH)
N16861242: J11.2 R517.1 T2.4(IN2)
N16861249: D113.2(CATHODE) D114.1(ANODE) T1.1(IN1) U53.6(CANL)
N16861268: J11.1 R517.2 T2.3(OUT2)
N16861373: D111.2 D112.2(CATHODE) D114.2(CATHODE)
N16900365: Q1.1(GATE) R537.1 R538.2
N16900541: C505.1 Q1.3(DRAIN) R536.1 U57.7(EN2)
N16908509: R540.2 R541.2 U57.19(PG1)
N16935004: R547.2 U57.8(RESET)
N17022031: C560.1 C561.1 C562.1 R549.1 U58.14(VCC)
N17025421: C563.1 C564.1 C565.1 R550.1 U59.14(VCC)
N17085418: R400.1 U28.154(GPIO84/SCITXDA)
N17096901: C237.2 R133.1 R488.1 R573.2
N17102058: C594.1 R495.1 R506.1 R574.2 R575.1
N17145229: C595.1 R599.2 U28.57(ADCIND1)
N17182974: C488.1 R49.1 R58.2 R528.1 R529.1
N17183073: C492.1 R532.2 R533.1 R534.1
N17183105: R532.1 U55.2(VO)
N17207390: C600.1 C601.1 C602.1 R612.1 U62.14(VCC)
N17215412: R679.1 U28.42(ADCINA1)
N17215422: R678.1 U28.43(ADCINA0)
N17215466: C691.2 DAC_5.1(DAC) R679.2 R681.2
N17215490: C690.2 DAC_4.1(DAC) R678.2 R680.2
N17215663: C687.2 DAC_1.1(DAC) R673.2 U28.47(ADCINB1)
N17215880: C598.1 R607.2 U28.44(ADCINCAL0)
N17228521: C698.1 R692.1 R693.1 R694.1 R695.2
N17238784: J4.6 R705.2
N17238858: C700.1 R696.2 R697.2 U28.38(ADCINA5)
N17241205: C701.1 R698.2 R699.2 U28.40(ADCINA3)
N17279598: T1.3(OUT2) T2.1(IN1)
N17279601: T1.4(IN2) T2.2(OUT1)
N17282960: J4.4 R704.2
N17283298: J4.2 R706.2

Not connected (* = marked no-connect by the designer): J4 8 9 10; U28 17(GPIO99) 19(GPIO9/EPWM5B/SCITXDB/SCIRXDA) 24(GPIO24) 25(GPIO25) 27(GPIO26) 28(GPIO27) 63(GPIO30/CANRXA) 64(GPIO28/SCIRXDA) 65(GPIO29/SCITXDA) 66(GPIO31/CANTXA) 67(GPIO32) 69(GPIO33) 70(GPIO34) 71(GPIO35) 73(FLT1) 74(FLT2) 83(GPIO36/SCITXDA/CANRXA) 84(GPIO37/CANTXA) 85(GPIO38/SCITXDC/CANTXB) 86(GPIO39/SCIRXDC/CANRXB) 87(GPIO40) 89(GPIO41) 90(GPIO48/SCITXDA) 92(ERRORSTS) 93(GPIO49/SCIRXDA) 94(GPIO50) 95(GPIO51) 96(GPIO52) 97(GPIO53) 98(GPIO54/SCITXDB) 100(GPIO55/SCIRXDB) 101(GPIO56/SCITXDC) 102(GPIO57/SCIRXDC) 103(GPIO58) 104(GPIO59) 105(GPIO60/SPISIMOB) 107(GPIO61/SPISOMIB) 110(GPIO64/SCIRXDA/SPISOMIB) 111(GPIO65/SCITXDA/SPICLKB) 112(GPIO66/SPISTEB) 113(GPIO44/EM1A4) 115(GPIO45/EM1A5) 118(GPIO133) 122(VSSOSC) 128(GPIO46/EM1A6/SCIRXDD) 129(GPIO47/EM1A7/SCITXDD) 130(GPIO42/SCITXDA/USB0DM) 131(GPIO43/USB0DP/SCIRXDA) 134(GPIO69/SPISIMOC/SCLB) 135(GPIO70/CANRXA/SCITXDB) 136(GPIO71/CANTXA/SCIRXDB/SPICLKC) 141(GPIO74) 142(GPIO75) 145(GPIO78) 146(GPIO79) 148(GPIO80) 149(GPIO81) 150(GPIO82) 151(GPIO83) 155(GPIO85/SCIRXDA) 156(GPIO86/SCITXDB/MCLKXA) 157(GPIO87/SCIRXDB) 161(GPIO1/EPWM1B) 163(GPIO3/EPWM2B) 165(GPIO5/EPWM3B) 167(GPIO7/EPWM4B) 170(GPIO88) 171(GPIO89/SCITXDC) 172(GPIO90/SCIRXDC); U57 4(NC) 5(MR) 17(NC2) 18(PG2) 20(NC1); U59 8(Y4) 9(A4) 10(Y5) 11(A5)

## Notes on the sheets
sheet 1
- Vin:800V-1.47V
- Max: 1.5V
- Vin:480V-0.82V
- NEAR DSP
- output  voltage sample
- NEAR DSP
- CAN
- OVP POINT: 860V
- AFE：1.8k 950V OVP
- DCDC：2.2k 860V OVP
- DC UVP
- NEAR DSP
- UVP POINT: 58V
- PCB Ver.: 02
- BOM Ver.: A
- Prepared by:
- Approved by:
- .
- Iris Liu
- Frank Wei
sheet 2
- Connect to  Simullator
- PCB Ver.: 02
- BOM Ver.: A
- Prepared by:
- .
- Iris Liu
- Approved by:
- Frank Wei
sheet 3
- 725V--->1.99V
- 900V--->2.48V
- bus voltage sam
- NearDSP
- 900V--->2.48V
- bus voltage sam
- NearDSP
- NearDSP
- E2PROM
- TEMPERATURE MEASUREMENT
- NearDSP
- NearDSP
- NearDSP
- NearDSP
- NearDSP
- NearDSP
- NearDSP
- PCB Ver.: 02
- BOM Ver.: A
- AC-LA-ADC: 1.1V
- AC-LB-ADC: 1.1V
- AC-LC-ADC: 1.1V
- Prepared by:
- .
- Iris Liu
- Approved by:
- Frank Wei
sheet 4
- Near DSP
- Near DSP
- JTAG
- PCB Ver.: 02
- BOM Ver.: A
- Prepared by:
- .
- Iris Liu
- Approved by:
- Frank Wei
- 5V Monitor, <4.2V turn off all PWM
